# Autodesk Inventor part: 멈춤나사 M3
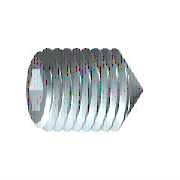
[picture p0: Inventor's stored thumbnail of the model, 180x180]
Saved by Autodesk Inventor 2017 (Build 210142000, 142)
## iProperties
Created: 2012-02
Part Number: 멈춤나사 M3
Material: 강철, 연강
Description: 6각 소켓 머리 없는 멈춤 나사
Document SubType Name: Modeling
Standard: KS B 1028
Designer: mduedu
Standards Organization: KS
Language: ko-KR
Size Designation: 원추점 M3x10
Categories: <MemberInstance><Categories><Category DisplayName="조임쇠" InternalName="e4da775c-781d-43d5-af7c-5136215cf5a6" Mnemonic="FSTN"><Category DisplayName="볼트" InternalN
Density: 7.86 g/cm^3
Mass: 0.471457 g
Surface Area: 1.07667 cm^2
Volume: 0.0599818 cm^3
Appearance: 강철
IsCustomPart: 1
Author: mduedu
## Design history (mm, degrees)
sketch "스케치1"
  geometry: L1 (0, 0)-(7.5, 0); L2 (10, 0.866)-(10, 1.5); L3 (10, 1.5)-(0, 1.5); L4 (10, 0.866)-(8, 0.866); L5 (8, 0.866)-(7.5, 0); L6 (0, -0.3)-(0, 1.8) reference; L7 (0, 1.5)-(0, 0)
  constraints: 13 end point, 3 parallel, 1 collinear, 1 perpendicular, 1 point on line
  dimensions: "d0" = 2 distance of L2.start L4.end (= INTI); "d1" = 60 deg angle of L5 L1; "d2" = 3 diameter of L3 L1 (= NND); "d3" = 1.73205 diameter of L4 L1 (= 1.1547 x SW); "d5" = 10 distance from line of L2 L3.end (= NLG)
revolve "본체" sketch "스케치1" stored, may be unused: angle "d6" = 90 deg
sketch "스케치2"
  geometry: L1 (-0.433, 0.75)-(0.433, 0.75); L2 (0.433, 0.75)-(0.866, 0); L3 (0.866, 0)-(0.433, -0.75); L4 (0.433, -0.75)-(-0.433, -0.75); L5 (-0.433, -0.75)-(-0.866, 0); L6 (-0.866, 0)-(-0.433, 0.75); 3 further points
  constraints: 12 end point, 1 coincident, 1 horizontal, 13 other
extrude "슬롯" join sketch "스케치2" taper "d7" = 0 deg; stored distance "d21" = 10
workaxis "Work Axis1"
workplane "Work Plane1"
sketch "스케치4"
  geometry: L1 (4.693, 1.5)-(5, 1.193) reference; L2 (5, 1.193)-(5, 0.866) reference; L3 (5, 0.866)-(3, 0.866) reference; L4 (3, 0.866)-(2.5, 0) reference; L5 (2.5, 0)-(3, -0.866) reference; L6 (3, -0.866)-(5, -0.866) reference; L7 (5, -0.866)-(5, -1.193) reference; L8 (5, -1.193)-(4.693, -1.5) reference; L9 (4.693, -1.5)-(-3.65, -1.5) reference; L10 (-3.65, -1.5)-(-5, -0.15) reference; L11 (-5, -0.15)-(-5, 0.15) reference; L12 (-5, 0.15)-(-3.65, 1.5) reference; L13 (-3.65, 1.5)-(4.693, 1.5) reference; L14 (-3.65, 1.5)-(-5.15, 0); L15 (-3.65, -1.5)-(-5.15, 0); 1 further point
  constraints: 4 end point, 2 collinear
  node "절단 모서리 투영1"
node "작업점1"
body "Solid1"
feature "스레드" dims "d12" = 10 (= NLG), "d13" = 0
chamfer "모따기1" distance "d8" = 1.35 (computed from NND, SPD, FAWI); stored, may be unused: angle "d9" = 45 deg (= FAWI), second distance "d34" = 1.35 (computed from NND, SPD, FAWI)
chamfer "모따기2" distance "d10" = 0.30673 (= -0.5 x GD1 + 0.5 x NND); stored, may be unused: angle "d11" = 45 deg (= FAWI), second distance "d35" = 0.30673 (= -0.5 x GD1 + 0.5 x NND)
other parameters: "NND" = 3 [user parameter; used in 5 equation terms], "NLG" = 10 [user parameter; used in 2 equation terms], "INTI" = 2 [user parameter; used in 1 equation term], "FAWI" = 45 deg [user parameter; used in 4 equation terms], "SW" = 1.5 [user parameter; used in 2 equation terms], "GD1" = 2.38655 (= THREADDIA - 1.2269 x PTC) [user parameter; used in 2 equation terms], "d4" = 0, "FAWI1" = 45 deg [user parameter], "SPD" = 0.3 [user parameter; used in 2 equation terms], "d36" = 0, "d37" = 0, "GUL" = 0.30673 (= 0.61345 x PTC) [user parameter], "TOA" = 30 deg [user parameter], "THREADDIA" = 3 [user parameter; used in 1 equation term], "PTC" = 0.5 [user parameter; used in 4 equation terms], "GAL" = 0.30673 (= 0.61345 x PTC) [user parameter], "E0" = 1.7325 (= 1.155 x SW) [user parameter]
